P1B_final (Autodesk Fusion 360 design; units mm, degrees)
part number: 2026-10-07-20-40-45-604
part number: 2026-10-09-11-22-32-824
part number: 2026-10-09-11-22-33-623
part number: 2026-10-09-11-22-36-860
part number: 2026-10-09-11-22-36-919
part number: 2026-10-09-11-22-37-526
part number: 2026-10-09-11-22-37-694
part number: 2026-10-09-11-22-37-958
part number: 2026-10-09-11-22-38-043
part number: 2026-10-09-11-22-38-120
part number: 2026-10-09-11-22-38-227
part number: 2026-10-09-11-22-38-316
part number: 2026-10-09-11-22-38-465
part number: 2026-10-09-11-22-38-509
part number: 2026-10-09-11-22-38-623
part number: 2026-10-09-11-22-38-719
part number: 2026-10-09-11-22-38-820
part number: 2026-10-09-11-22-38-844
part number: 2026-10-09-11-22-38-866
part number: 2026-10-09-11-22-39-133
parameter "gimbal_clear" = 4
parameter "ring_w" = 5 comment "DESIGN: ring band radial width"
parameter "ring_t" = 3 comment "DESIGN: ring band thickness (axial)"
parameter "ring_gap" = 5 comment "DESIGN: radial gap between inner ring outside and outer ring inside"
parameter "junction_len" = 14 comment "DESIGN: junction block length along the ring"
parameter "junction_t" = 8 comment "DESIGN: junction block thickness (holds the 5 mm bearing)"
parameter "splice_len" = 14 comment "DESIGN: splice plate overlap onto each quarter end"
parameter "splice_t" = 2 comment "DESIGN: splice plate thickness"
parameter "lighten_w" = 2.6 comment "DESIGN: lightening slot width in ring quarters"
parameter "bearing_od" = 5 comment "MEASURE: MR52ZZ outer diameter"
parameter "bearing_w" = 2.5 comment "MEASURE: MR52ZZ width"
parameter "bearing_seat_clear" = 0.3 (= "5.30 mm - bearing_od")
parameter "pin_d" = 2 comment "MEASURE: dowel pin diameter (2 x 16 mm)"
parameter "pin_press_d" = 1.9
parameter "pin_press_depth" = 6 comment "DESIGN: pin press depth"
parameter "pin_len" = 16 comment "MEASURE: dowel pin length"
parameter "pivot_gap" = 1
parameter "pole_boss_len" = 8 comment "DESIGN: pole hub pin boss length (inward)"
parameter "pole_boss_od" = 6 comment "DESIGN: pole hub pin boss OD"
parameter "pivot_boss_od" = 7 comment "DESIGN: arm-end pivot boss OD"
parameter "pivot_boss_len" = 12
parameter "pivot_plate_t" = 4 comment "DESIGN: arm-end pivot plate thickness"
parameter "cg_slot" = 5 comment "[P1B] DESIGN: vertical CG travel each way at the arm-end pivot plates"
parameter "cage_outer_dia" = 247.8458 (= "2 * ( cage_vertex_r + hub_core_r )") comment "DERIVED (target 245-250): maximum assembled outside span including hubs"
parameter "rod_dia" = 1 comment "MEASURE: actual carbon rod diameter (1 mm prototype baseline)"
parameter "rod_bore_clear" = 0.1375 (= "( 1.275 mm - rod_dia ) / 2") comment "FIT COUPON: socket clearance per side (strip prints 0.05-0.30)"
parameter "hub_core_r" = 2.5 comment "DESIGN: hub centre to flat outer face (sets outer span; bed face when printing)"
parameter "hub_body_r" = 2.2 comment "DESIGN: hub core cylinder radius"
parameter "hub_arm_len" = 7 comment "DESIGN: hub centre to socket mouth (original ~10 mm for 3 mm rod)"
parameter "hub_arm_od" = 3.2 comment "DESIGN: socket tube OD (original ~5 mm for 3 mm rod)"
parameter "socket_depth" = 5 comment "FIT COUPON: rod insertion depth (original ~7.8 mm)"
parameter "rod_end_gap" = 0.25 comment "DESIGN: gap between rod end and socket floor"
parameter "cage_vertex_r" = 121.4229 (= "cage_edge * 2.4780186591") comment "DERIVED: hub centre radius"
parameter "cage_edge" = 49 (= "rod_cut_len + 2 * ( hub_arm_len - socket_depth ) + 2 * rod_end_gap") comment "DERIVED: hub centre-to-centre distance"
parameter "rod_cut_len" = 44.5 comment "DESIGN: cut length of the 90 edge rods; drives the cage size"
parameter "pent_r" = 41.6819 (= "cage_edge / ( 2 * sin(36 deg) )") comment "DERIVED: pentagon circumradius"
parameter "pole_rise" = 7.3784 (= "cage_vertex_r - sqrt(cage_vertex_r ^ 2 - pent_r ^ 2)") comment "DERIVED: pole hub height above its pentagon"
parameter "pole_edge" = 42.3299 (= "sqrt(pent_r ^ 2 + pole_rise ^ 2)") comment "DERIVED: pole hub to four-way hub distance"
parameter "pole_rod_cut_len" = 37.8299 (= "pole_edge - 2 * ( hub_arm_len - socket_depth ) - 2 * rod_end_gap") comment "DERIVED: cut length of the 10 pole rods"
parameter "motor_diag" = 95 comment "MEASURE: diagonal motor-centre distance (Apex-2 ~95)"
parameter "prop_dia" = 50.8 comment "MEASURE: actual prop diameter (Gemfan 2015)"
parameter "prop_z" = 8.9 comment "MEASURE: prop disk bottom above frame top"
parameter "prop_disk_h" = 5.1 comment "DESIGN: prop swept-disk thickness"
parameter "motor_od" = 15.84 comment "MEASURE: motor bell OD"
parameter "motor_h" = 8.9 comment "MEASURE: motor height above frame top"
parameter "frame_t" = 2.5 comment "MEASURE: frame plate thickness"
parameter "arm_w" = 8 comment "MEASURE: frame arm width"
parameter "stack_w" = 33 comment "MEASURE: frame centre plate width"
parameter "stack_h" = 12 comment "MEASURE: stack height above frame top"
parameter "frame_hole_pitch" = 25.5 comment "MEASURE: frame/AIO square mounting-hole pitch"
parameter "cam_size" = 14 comment "MEASURE: camera body (14 x 14 class)"
parameter "cam_y" = 22 comment "MEASURE: camera centre forward (+Y) of frame centre"
parameter "cam_z" = 9 comment "MEASURE: camera centre above frame top"
parameter "cam_tilt" = 20 comment "SETUP: camera uptilt"
parameter "cam_hfov" = 160 comment "MEASURE: lens horizontal field of view (cone approximation)"
parameter "batt450_l" = 62.8 comment "MEASURE: OVONIC 450 mAh pack length"
parameter "batt450_w" = 16.4 comment "MEASURE: 450 mAh pack width"
parameter "batt450_h" = 13.8 comment "MEASURE: 450 mAh pack height"
parameter "batt1100_l" = 56.56 comment "MEASURE: OVONIC 1100 mAh pack length"
parameter "batt1100_w" = 23.5 comment "MEASURE: 1100 mAh pack width"
parameter "batt1100_h" = 18.4 comment "MEASURE: 1100 mAh pack height"
parameter "carrier_t" = 2.5 comment "DESIGN: carrier plate thickness"
parameter "carrier_len" = 40 comment "DESIGN: carrier centre length (Y)"
parameter "carrier_core_w" = 48 comment "[P1B] DESIGN: carrier centre width (strap slots clear the lateral frame slots)"
parameter "carrier_span" = 80 comment "DESIGN: carrier tip-to-tip span along X"
parameter "carrier_bar_w" = 12 comment "DESIGN: carrier side-bar width"
parameter "adj_y" = 2 comment "[P1B] DESIGN: frame travel each way across the arms (lateral)"
parameter "adj_x" = 3
parameter "strap_w" = 12.5 comment "MEASURE: battery strap width"
parameter "strap_slot_t" = 2.5 comment "MEASURE: battery strap thickness + clearance"
parameter "support_w" = 6 comment "DESIGN: support arm width"
parameter "support_h" = 4 comment "DESIGN: support arm height"
parameter "flange_h" = 16 comment "DESIGN: support end flange height"
parameter "flange_t" = 3 comment "DESIGN: support end flange thickness"
parameter "bracket_t" = 3 comment "DESIGN: X bracket thickness"
parameter "bracket_bar_w" = 7 comment "DESIGN: X bracket bar width"
parameter "mount_boss_len" = 6 comment "DESIGN: boss length inward from mount-hub centre"
parameter "mount_boss_od" = 5 comment "DESIGN: mount boss OD"
parameter "m2_clear" = 2.3 comment "DESIGN: M2 clearance hole / slot width"
parameter "m2_tap" = 2 comment "FIT COUPON: M2 self-tapping pilot (strip prints 1.6/1.7/1.8)"
parameter "print_wall" = 1.2 comment "ASSUMED: slicer wall/skin thickness for the print-mass estimate (3 x 0.4 mm)"
parameter "antenna_len" = 30 comment "MEASURE: exposed VTX antenna element (listing: 70 mm overall incl. coax)"
parameter "antenna_d" = 5 comment "MEASURE: VTX antenna element diameter"
parameter "hub_keel_w" = 1.6
parameter "battery_gap" = 3
parameter "frame_column_h" = 20
parameter "battery_shield_t" = 0.8
parameter "pin_press_horizontal_d" = 2.15
parameter "pin_press_vertical_d" = 2.25
base_feature "Base Feature1" bodies "rods_edge_x90_cut_44.50mm", "rods_pole_x10_cut_37.83mm", "HUB_ENVELOPE_spheres"
sketch "cage_wireframe (hub centre lines)" plane through (0, 0, 0) normal (0, 0, 1) x axis (1, 0, 0)
  line L1 (-49, 67.4427) -> (-24.5, 33.7214)
  line L2 (-39.6418, -12.8804) -> (-24.5, 33.7214)
  line L3 (24.5, 33.7214) -> (-24.5, 33.7214)
  line L4 (-88.6418, 54.5623) -> (-49, 67.4427)
  line L5 (-24.5, 101.1641) -> (-49, 67.4427)
  line L6 (-79.2837, -25.7608) -> (-39.6418, -12.8804)
  line L7 (0, -41.6819) -> (-39.6418, -12.8804)
  line L8 (-103.7837, 7.9605) -> (-79.2837, -25.7608)
  line L9 (-79.2837, -67.4427) -> (-79.2837, -25.7608)
  line L10 (79.2837, -25.7608) -> (39.6418, -12.8804)
  line L11 (0, -41.6819) -> (39.6418, -12.8804)
  line L12 (24.5, 33.7214) -> (39.6418, -12.8804)
  line L13 (79.2837, -67.4427) -> (79.2837, -25.7608)
  line L14 (103.7837, 7.9605) -> (79.2837, -25.7608)
  line L15 (0, -83.3638) -> (0, -41.6819)
  line L16 (-39.6418, -96.2442) -> (0, -83.3638)
  line L17 (39.6418, -96.2442) -> (0, -83.3638)
  line L18 (49, 67.4427) -> (24.5, 33.7214)
  line L19 (24.5, 101.1641) -> (49, 67.4427)
  line L20 (88.6418, 54.5623) -> (49, 67.4427)
  line L21 (-103.7837, 7.9605) -> (-88.6418, 54.5623)
  line L22 (-88.6418, 80.3231) -> (-88.6418, 54.5623)
  line L23 (-118.9255, -12.8804) -> (-103.7837, 7.9605)
  line L24 (-24.5, 117.0851) -> (-49, 109.1246)
  line L25 (-24.5, 101.1641) -> (-49, 109.1246)
  line L26 (-88.6418, 80.3231) -> (-49, 109.1246)
  line L27 (24.5, 117.0851) -> (-24.5, 117.0851)
  line L28 (-39.6418, 96.2442) -> (-24.5, 117.0851)
  line L29 (24.5, 101.1641) -> (-24.5, 101.1641)
  line L30 (49, 109.1246) -> (24.5, 101.1641)
  line L31 (-103.7837, 59.4822) -> (-88.6418, 80.3231)
  line L32 (-118.9255, 12.8804) -> (-103.7837, 59.4822)
  line L33 (-79.2837, 67.4427) -> (-103.7837, 59.4822)
  line L34 (-88.6418, -80.3231) -> (-103.7837, -59.4822)
  line L35 (-79.2837, -67.4427) -> (-103.7837, -59.4822)
  line L36 (-118.9255, -12.8804) -> (-103.7837, -59.4822)
  line L37 (-49, -109.1246) -> (-88.6418, -80.3231)
  line L38 (-88.6418, -54.5623) -> (-88.6418, -80.3231)
  line L39 (-39.6418, -96.2442) -> (-79.2837, -67.4427)
  line L40 (-24.5, -117.0851) -> (-39.6418, -96.2442)
  line L41 (-118.9255, 12.8804) -> (-118.9255, -12.8804)
  line L42 (-103.7837, -7.9605) -> (-118.9255, 12.8804)
  line L43 (49, 109.1246) -> (24.5, 117.0851)
  line L44 (39.6418, 96.2442) -> (24.5, 117.0851)
  line L45 (88.6418, 80.3231) -> (49, 109.1246)
  line L46 (-79.2837, 67.4427) -> (-39.6418, 96.2442)
  line L47 (0, 83.3638) -> (-39.6418, 96.2442)
  line L48 (-79.2837, 25.7608) -> (-79.2837, 67.4427)
  line L49 (0, 41.6819) -> (0, 83.3638)
  line L50 (39.6418, 96.2442) -> (0, 83.3638)
  line L51 (-39.6418, 12.8804) -> (0, 41.6819)
  line L52 (39.6418, 12.8804) -> (0, 41.6819)
  line L53 (79.2837, 67.4427) -> (39.6418, 96.2442)
  line L54 (103.7837, 59.4822) -> (79.2837, 67.4427)
  line L55 (79.2837, 25.7608) -> (79.2837, 67.4427)
  line L56 (-24.5, -117.0851) -> (-49, -109.1246)
  line L57 (-24.5, -101.1641) -> (-49, -109.1246)
  line L58 (24.5, -117.0851) -> (-24.5, -117.0851)
  line L59 (-103.7837, -7.9605) -> (-88.6418, -54.5623)
  line L60 (-49, -67.4427) -> (-88.6418, -54.5623)
  line L61 (-79.2837, 25.7608) -> (-103.7837, -7.9605)
  line L62 (-24.5, -33.7214) -> (-49, -67.4427)
  line L63 (-24.5, -101.1641) -> (-49, -67.4427)
  line L64 (-39.6418, 12.8804) -> (-24.5, -33.7214)
  line L65 (24.5, -33.7214) -> (-24.5, -33.7214)
  line L66 (24.5, -101.1641) -> (-24.5, -101.1641)
  line L67 (49, -109.1246) -> (24.5, -101.1641)
  line L68 (49, -67.4427) -> (24.5, -101.1641)
  line L69 (39.6418, -96.2442) -> (79.2837, -67.4427)
  line L70 (103.7837, -59.4822) -> (79.2837, -67.4427)
  line L71 (24.5, -117.0851) -> (39.6418, -96.2442)
  line L72 (88.6418, 54.5623) -> (103.7837, 7.9605)
  line L73 (118.9255, -12.8804) -> (103.7837, 7.9605)
  line L74 (88.6418, 80.3231) -> (88.6418, 54.5623)
  line L75 (88.6418, -80.3231) -> (103.7837, -59.4822)
  line L76 (118.9255, -12.8804) -> (103.7837, -59.4822)
  line L77 (49, -109.1246) -> (88.6418, -80.3231)
  line L78 (88.6418, -54.5623) -> (88.6418, -80.3231)
  line L79 (118.9255, 12.8804) -> (118.9255, -12.8804)
  line L80 (103.7837, 59.4822) -> (118.9255, 12.8804)
  line L81 (103.7837, -7.9605) -> (118.9255, 12.8804)
  line L82 (49, -109.1246) -> (24.5, -117.0851)
  line L83 (103.7837, 59.4822) -> (88.6418, 80.3231)
  line L84 (-39.6418, 12.8804) -> (-79.2837, 25.7608)
  line L85 (49, -67.4427) -> (24.5, -33.7214)
  line L86 (39.6418, 12.8804) -> (24.5, -33.7214)
  line L87 (88.6418, -54.5623) -> (49, -67.4427)
  line L88 (79.2837, 25.7608) -> (39.6418, 12.8804)
  line L89 (103.7837, -7.9605) -> (79.2837, 25.7608)
  line L90 (103.7837, -7.9605) -> (88.6418, -54.5623)
  line L91 (-24.5, 33.7214) -> (0, 0)
  line L92 (-39.6418, -12.8804) -> (0, 0)
  line L93 (39.6418, -12.8804) -> (0, 0)
  line L94 (0, -41.6819) -> (0, 0)
  line L95 (24.5, 33.7214) -> (0, 0)
  line L96 (0, 41.6819) -> (0, 0)
  line L97 (-24.5, -33.7214) -> (0, 0)
  line L98 (-39.6418, 12.8804) -> (0, 0)
  line L99 (24.5, -33.7214) -> (0, 0)
  line L100 (39.6418, 12.8804) -> (0, 0)
base_feature "Base Feature1" bodies "hub_3way"
copy_paste "CopyPaste1"
copy_paste "CopyPaste2"
copy_paste "CopyPaste3"
copy_paste "CopyPaste4"
copy_paste "CopyPaste5"
copy_paste "CopyPaste6"
copy_paste "CopyPaste7"
copy_paste "CopyPaste8"
copy_paste "CopyPaste9"
copy_paste "CopyPaste10"
copy_paste "CopyPaste11"
copy_paste "CopyPaste12"
copy_paste "CopyPaste13"
copy_paste "CopyPaste14"
copy_paste "CopyPaste15"
copy_paste "CopyPaste16"
copy_paste "CopyPaste17"
copy_paste "CopyPaste18"
copy_paste "CopyPaste19"
copy_paste "CopyPaste20"
copy_paste "CopyPaste21"
copy_paste "CopyPaste22"
copy_paste "CopyPaste23"
copy_paste "CopyPaste24"
copy_paste "CopyPaste25"
copy_paste "CopyPaste26"
copy_paste "CopyPaste27"
copy_paste "CopyPaste28"
copy_paste "CopyPaste29"
copy_paste "CopyPaste30"
copy_paste "CopyPaste31"
copy_paste "CopyPaste32"
copy_paste "CopyPaste33"
copy_paste "CopyPaste34"
copy_paste "CopyPaste35"
copy_paste "CopyPaste36"
copy_paste "CopyPaste37"
copy_paste "CopyPaste38"
copy_paste "CopyPaste39"
copy_paste "CopyPaste40"
copy_paste "CopyPaste41"
copy_paste "CopyPaste42"
copy_paste "CopyPaste43"
copy_paste "CopyPaste44"
copy_paste "CopyPaste45"
base_feature "Base Feature1" bodies "hub_3way_mount_A"
copy_paste "CopyPaste46"
copy_paste "CopyPaste47"
copy_paste "CopyPaste48"
base_feature "Base Feature1" bodies "hub_4way"
copy_paste "CopyPaste49"
copy_paste "CopyPaste50"
copy_paste "CopyPaste51"
copy_paste "CopyPaste52"
copy_paste "CopyPaste53"
copy_paste "CopyPaste54"
copy_paste "CopyPaste55"
copy_paste "CopyPaste56"
copy_paste "CopyPaste57"
base_feature "Base Feature1" bodies "hub_pole_5way_pivot"
copy_paste "CopyPaste58"
base_feature "Base Feature1" bodies "outer_ring_quarter"
copy_paste "CopyPaste1"
copy_paste "CopyPaste2"
copy_paste "CopyPaste3"
base_feature "Base Feature1" bodies "outer_junction_X_bearing"
copy_paste "CopyPaste4"
base_feature "Base Feature1" bodies "outer_junction_Z_bearing"
copy_paste "CopyPaste5"
base_feature "Base Feature1" bodies "inner_ring_quarter"
copy_paste "CopyPaste1"
copy_paste "CopyPaste2"
copy_paste "CopyPaste3"
base_feature "Base Feature1" bodies "inner_junction_Y_bearing"
copy_paste "CopyPaste4"
base_feature "Base Feature1" bodies "inner_junction_X_pin"
copy_paste "CopyPaste5"
base_feature "Base Feature1" bodies "frame_plate_PLACEHOLDER", "motors_x4_PLACEHOLDER", "PROP_DISK_FR_keepout", "PROP_DISK_FL_keepout", "PROP_DISK_RL_keepout", "PROP_DISK_RR_keepout", "stack_AIO_PLACEHOLDER", "camera_PLACEHOLDER"
base_feature "Base Feature1" bodies "carrier_plate"
base_feature "Base Feature1" bodies "nut_shield_plate"
base_feature "Base Feature1" bodies "support_arm_p1b"
copy_paste "CopyPaste1"
base_feature "Base Feature1" bodies "arm_pivot_block"
copy_paste "CopyPaste1"
base_feature "Base Feature1" bodies "pin_4", "pin_5"
base_feature "Base Feature1" bodies "MR52ZZ_2", "MR52ZZ_3", "MR52ZZ_4", "MR52ZZ_5"
base_feature "Base Feature1" bodies "MR52ZZ_0", "MR52ZZ_1", "pin_2", "pin_3"
base_feature "Base Feature1" bodies "pin_0", "pin_1"
base_feature "Base Feature1" bodies "gimbal_fit_coupon"
ground "Pin"
as_built_joint "As-built1"
as_built_joint "As-built1"
as_built_joint "As-built1"
as_built_joint "As-built1"
as_built_joint "As-built43"
as_built_joint "As-built44"
as_built_joint "As-built45"
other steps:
create_component "CreateComponent119"
create_component "CreateComponent1"
create_component "CreateComponent2"
create_component "CreateComponent1"
create_component "CreateComponent2"
create_component "CreateComponent3"
create_component "CreateComponent4"
create_component "CreateComponent120"
create_component "CreateComponent1"
create_component "CreateComponent2"
create_component "CreateComponent3"
create_component "CreateComponent121"
create_component "CreateComponent1"
create_component "CreateComponent2"
create_component "CreateComponent3"
create_component "CreateComponent122"
create_component "CreateComponent1"
create_component "CreateComponent1"
create_component "CreateComponent2"
create_component "CreateComponent1"
create_component "CreateComponent2"
create_component "CreateComponent3"
create_component "CreateComponent3"
create_component "CreateComponent3"
create_component "CreateComponent4"
create_component "CreateComponent4"
create_component "CreateComponent4"
create_component "CreateComponent123"
named bodies: "rods_edge_x90_cut_44.50mm", "rods_pole_x10_cut_37.83mm", "HUB_ENVELOPE_spheres", "hub_3way", "hub_3way_mount_A", "hub_4way", "hub_pole_5way_pivot", "outer_ring_quarter", "outer_junction_X_bearing", "outer_junction_Z_bearing", "inner_ring_quarter", "inner_junction_Y_bearing", "inner_junction_X_pin", "frame_plate_PLACEHOLDER", "motors_x4_PLACEHOLDER", "PROP_DISK_FR_keepout", "PROP_DISK_FL_keepout", "PROP_DISK_RL_keepout", "PROP_DISK_RR_keepout", "stack_AIO_PLACEHOLDER", "camera_PLACEHOLDER", "CAMERA_VIEW_cone", "ANTENNA_element_PLACEHOLDER", "M2_nut_and_tail_x4_envelope", "M2_nut_arm_x4_envelope", "BATTERY_PAD_foam", "battery_450mAh_PLACEHOLDER", "battery_1100mAh_PLACEHOLDER", "carrier_plate", "nut_shield_plate", "support_arm_p1b", "arm_pivot_block", "pin_4", "pin_5", "MR52ZZ_2", "MR52ZZ_3", "MR52ZZ_4", "MR52ZZ_5", "MR52ZZ_0", "MR52ZZ_1", "pin_2", "pin_3", "pin_0", "pin_1", "gimbal_fit_coupon"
